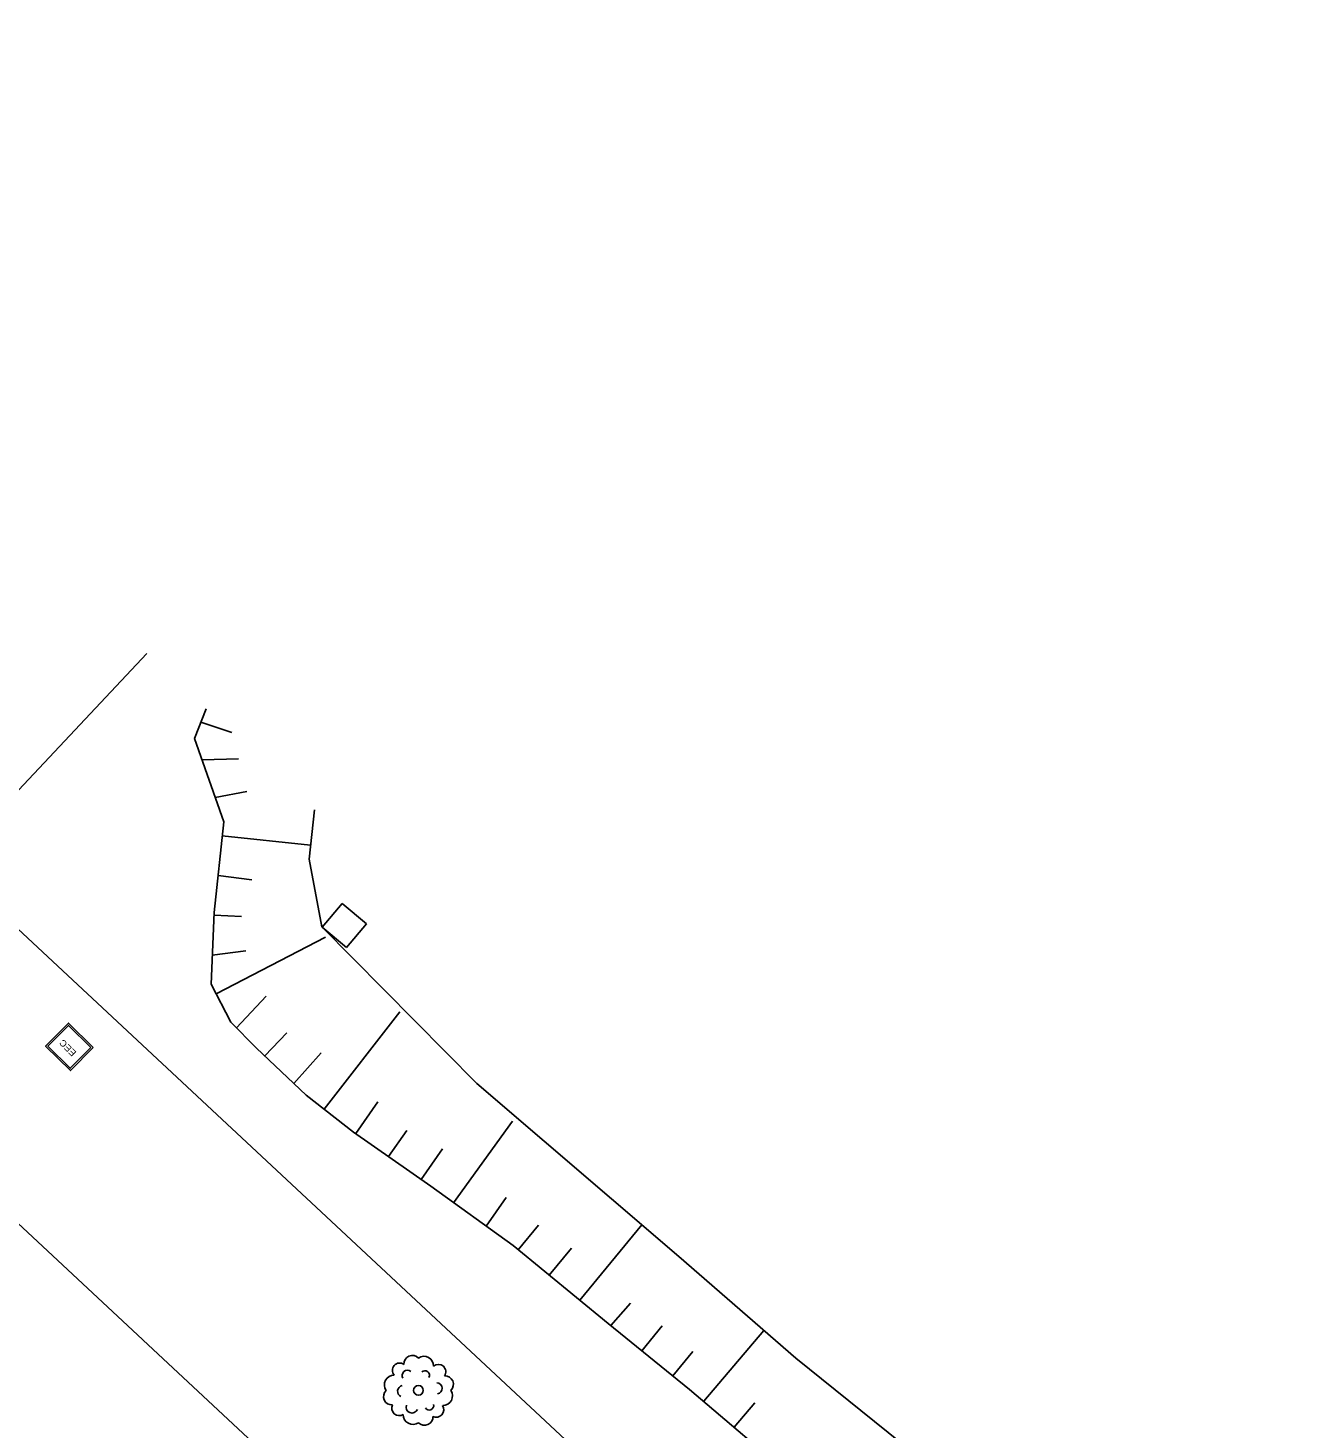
# Model space of a CAD drawing. Extents: x 343997 to 344255, y 298512 to 298767.
# Drawn here: x 344119.67 to 344151.36, y 298730.51 to 298765.59 of the extents above; entities that cross this region are included whole.
import ezdxf

# ---------------------------------------------------------------- set-up
doc = ezdxf.new("R2010")
doc.units = 0
for name, color, linetype in [('Default', 7, 'Continuous'), ('DH_CADRE -CARTOUCHE', 7, 'Continuous'), ('DH_CADRE-CARTOUCHE', 7, 'Continuous'), ('DH_CADRE-CARTOUCHE-NORD', 7, 'Continuous'), ('PC_REBAR', 7, 'Continuous'), ('PS_OBJECT', 7, 'Continuous'), ('PS_PLATE', 7, 'Continuous'), ('RES_ELECTRICITE', 7, 'Continuous')]:
    doc.layers.add(name, color=color, linetype=linetype)

# ---------------------------------------------------------------- blocks, each defined once
blk = doc.blocks.new('R3')
at = {"layer": 'Default'}
for p, q in [((0, 0.1), (0.1, 0.1)), ((0, 0), (0, 0.1)), ((0.1, 0.1), (0.1, 0)), ((0.1, 0), (0, 0))]:
    blk.add_line(p, q, dxfattribs=at)
blk = doc.blocks.new('RES_ELECTRICITE')
at = {"layer": 'RES_ELECTRICITE'}
for points in [[(0, 0), (0, 0.1), (0.1, 0.1), (0.1, 0)], [(0.005, 0.005), (0.005, 0.095), (0.095, 0.095), (0.095, 0.005)]]:
    blk.add_lwpolyline(points, close=True, dxfattribs=at)
blk.add_text('EEC', height=0.02, dxfattribs=at).set_placement((0.0237, 0.046))
blk = doc.blocks.new('ARB1')
at = {"layer": 'Default'}
blk.add_circle((0, 0), 0.0122, dxfattribs=at)
for centre, radius, start, end in [((-0.0153, 0.0664), 0.0211, 43.6925, 183.5969), ((0.0139, 0.0613), 0.0241, 358.4583, 125.1928), ((-0.0613, 0.0139), 0.0241, 88.4583, 215.1928), ((-0.0471, 0.0503), 0.0183, 53.9554, 222.2066), ((-0.0276, 0.037), 0.0134, 52.4396, 209.5496), ((0.0164, 0.038), 0.0112, 330.5895, 133.7127), ((0.0501, 0.0468), 0.0183, 325.1444, 131.0175), ((0.0664, 0.0153), 0.0211, 313.6925, 93.5969), ((-0.0373, -0.0024), 0.0149, 103.7092, 242.3465), ((0.0458, 0.0052), 0.0137, 276.6214, 88.967), ((0.0613, -0.0139), 0.0241, 268.4583, 35.1928), ((-0.0664, -0.0153), 0.0211, 133.6925, 273.5969), ((-0.0478, -0.0443), 0.019, 155.2243, 300.9377), ((-0.0139, -0.0613), 0.0241, 178.4583, 305.1928), ((-0.0163, -0.042), 0.0148, 159.5371, 338.1663), ((0.0153, -0.0664), 0.0211, 223.6925, 3.5969), ((0.0271, -0.038), 0.0112, 210.5895, 13.7127), ((0.0448, -0.0483), 0.0188, 243.1323, 33.0297)]:
    blk.add_arc(centre, radius, start, end, dxfattribs=at)

msp = doc.modelspace()

# ---------------------------------------------------------------- linework, layer by layer
at = {"layer": 'DH_CADRE -CARTOUCHE'}
msp.add_lwpolyline([(343997.309, 298660.673), (344147.183, 298520.807), (344245.09, 298625.72), (344095.215, 298765.586)], close=True, dxfattribs=at)
at = {"layer": 'DH_CADRE-CARTOUCHE'}
msp.add_lwpolyline([(344122.649, 298749.916), (344119.175, 298746.216), (344104.333, 298729.921), (344103.629, 298728.425), (344103.178, 298726.908), (344102.994, 298725.349), (344103.009, 298724.152), (344103.293, 298722.366), (344103.622, 298721.156), (344104.336, 298719.642), (344105.154, 298718.475), (344128.542, 298697.099), (344156.76, 298672.229), (344158.923, 298671.699), (344160.816, 298671.605), (344163.478, 298672.279), (344165.611, 298673.484), (344167.1, 298674.65), (344168.229, 298675.97), (344184.084, 298692.584)], dxfattribs=at)
at = {"layer": 'PS_OBJECT'}
for p, q in [((344124.002, 298748.19), (344124.775, 298747.932)), ((344124.029, 298747.25), (344124.946, 298747.275)), ((344124.359, 298746.306), (344125.155, 298746.455)), ((344124.536, 298745.344), (344126.749, 298745.109)), ((344124.43, 298744.349), (344125.274, 298744.24)), ((344124.329, 298743.354), (344125.021, 298743.324)), ((344124.382, 298741.386), (344127.118, 298742.804)), ((344124.286, 298742.355), (344125.123, 298742.46)), ((344124.89, 298740.533), (344125.639, 298741.326)), ((344127.088, 298738.494), (344128.986, 298740.937)), ((344125.602, 298739.831), (344126.154, 298740.41)), ((344126.326, 298739.14), (344127.014, 298739.909)), ((344127.88, 298737.883), (344128.43, 298738.677)), ((344128.698, 298737.308), (344129.158, 298737.963)), ((344130.331, 298736.152), (344131.804, 298738.193)), ((344129.517, 298736.734), (344130.049, 298737.501)), ((344131.142, 298735.567), (344131.649, 298736.285)), ((344131.947, 298734.973), (344132.453, 298735.593)), ((344133.496, 298733.707), (344135.044, 298735.6)), ((344132.721, 298734.34), (344133.287, 298735.012)), ((344134.27, 298733.074), (344134.763, 298733.637)), ((344135.047, 298732.444), (344135.551, 298733.066)), ((344136.594, 298731.176), (344138.105, 298732.95)), ((344135.824, 298731.815), (344136.321, 298732.427)), ((344137.356, 298730.527), (344137.875, 298731.136))]:
    msp.add_line(p, q, dxfattribs=at)
for points in [[(344146.792, 298719.679), (344146.928, 298720.992), (344146.442, 298722.409), (344144.219, 298724.371), (344141.652, 298726.758), (344138.951, 298729.169), (344136.242, 298731.476), (344134.201, 298733.13), (344131.821, 298735.077), (344129.756, 298736.567), (344127.823, 298737.923), (344126.636, 298738.844), (344125.396, 298740.027), (344124.752, 298740.672), (344124.255, 298741.632), (344124.332, 298743.426), (344124.573, 298745.693), (344123.844, 298747.78), (344124.134, 298748.531)], [(344126.849, 298745.997), (344126.71, 298744.759), (344127.026, 298743.068), (344130.916, 298739.136), (344135.968, 298734.808), (344138.904, 298732.255), (344141.857, 298729.875), (344143.823, 298728.108), (344146.055, 298726.342), (344147.327, 298725.192), (344148.161, 298724.497), (344148.568, 298723.821), (344148.724, 298723.034), (344148.613, 298722.231), (344148.361, 298721.682), (344147.974, 298721.092), (344146.792, 298719.679)]]:
    msp.add_lwpolyline(points, dxfattribs=at)
at = {"layer": 'PS_PLATE'}
msp.add_lwpolyline([(344136.362, 298708.941), (344141.75, 298714.784), (344118.651, 298736.353), (344113.24, 298730.553)], close=True, dxfattribs=at)

# ---------------------------------------------------------------- block references
at = {"layer": 'DH_CADRE-CARTOUCHE-NORD', "xscale": 7.96476983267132, "yscale": -7.7639017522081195, "rotation": -40.01382}
msp.add_blockref('R3', (344127.539, 298743.651), dxfattribs=at)
at = {"layer": 'PC_REBAR', "xscale": 10, "yscale": 10}
msp.add_blockref('ARB1', (344129.45, 298731.45), dxfattribs=at)
at = {"layer": 'RES_ELECTRICITE', "xscale": 8.734508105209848, "yscale": 8.114148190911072, "rotation": 135.23034408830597}
msp.add_blockref('RES_ELECTRICITE', (344121.302, 298740.039), dxfattribs=at)

doc.saveas('drawing.dxf')
